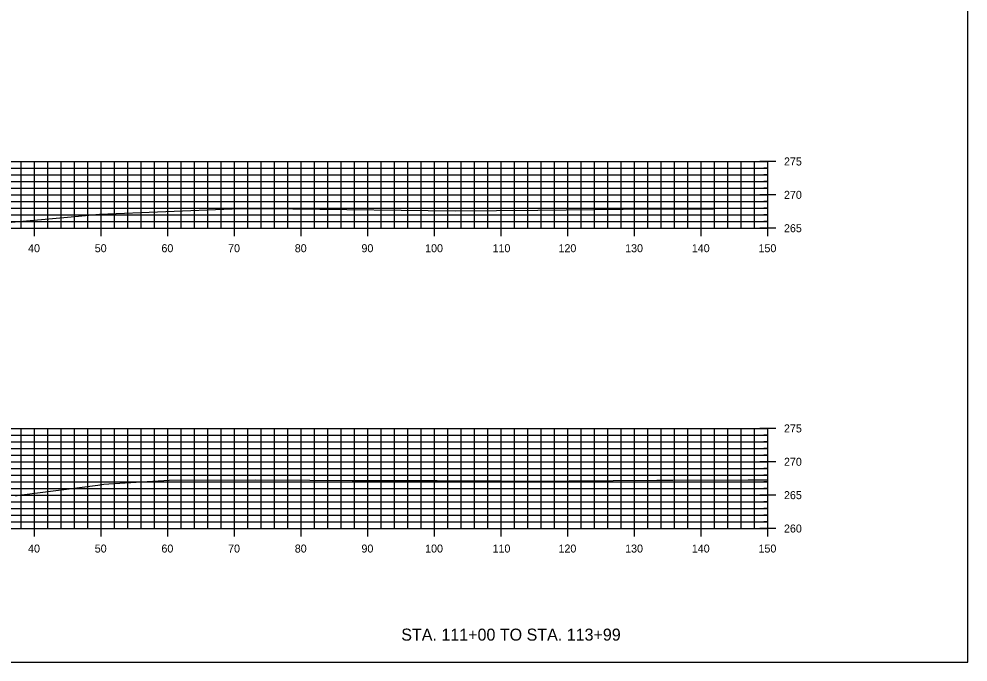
# Model space of a CAD drawing. Extents: x 1661012 to 1662122, y 670053 to 671852.
# Drawn here: x 1661629.7 to 1661772, y 671274.1 to 671370.5 of the extents above; entities that cross this region are included whole.
import ezdxf

# ---------------------------------------------------------------- set-up
doc = ezdxf.new("R2010")
doc.units = 0
for name, color, linetype in [('R_Concrete', 7, 'Continuous'), ('R_Concrete Hidden', 7, 'Continuous'), ('R_Erosion', 7, 'Continuous'), ('R_Exist Surface', 7, 'Continuous'), ('R_Proposed Road', 7, 'Continuous')]:
    doc.layers.add(name, color=color, linetype=linetype)

msp = doc.modelspace()

# ---------------------------------------------------------------- linework, layer by layer
at = {"layer": 'R_Concrete'}
for p, q in [((1661441.99, 671349.12), (1661741.99, 671349.12)), ((1661629.99, 671339.12), (1661629.99, 671349.12)), ((1661631.99, 671339.12), (1661631.99, 671349.12)), ((1661633.99, 671339.12), (1661633.99, 671349.12)), ((1661635.99, 671339.12), (1661635.99, 671349.12)), ((1661637.99, 671339.12), (1661637.99, 671349.12)), ((1661639.99, 671339.12), (1661639.99, 671349.12)), ((1661641.99, 671339.12), (1661641.99, 671349.12)), ((1661643.99, 671339.12), (1661643.99, 671349.12)), ((1661645.99, 671339.12), (1661645.99, 671349.12)), ((1661647.99, 671339.12), (1661647.99, 671349.12)), ((1661649.99, 671339.12), (1661649.99, 671349.12)), ((1661651.99, 671339.12), (1661651.99, 671349.12)), ((1661653.99, 671339.12), (1661653.99, 671349.12)), ((1661655.99, 671339.12), (1661655.99, 671349.12)), ((1661657.99, 671339.12), (1661657.99, 671349.12)), ((1661659.99, 671339.12), (1661659.99, 671349.12)), ((1661661.99, 671339.12), (1661661.99, 671349.12)), ((1661663.99, 671339.12), (1661663.99, 671349.12)), ((1661665.99, 671339.12), (1661665.99, 671349.12)), ((1661667.99, 671339.12), (1661667.99, 671349.12)), ((1661669.99, 671339.12), (1661669.99, 671349.12)), ((1661671.99, 671339.12), (1661671.99, 671349.12)), ((1661673.99, 671339.12), (1661673.99, 671349.12)), ((1661675.99, 671339.12), (1661675.99, 671349.12)), ((1661677.99, 671339.12), (1661677.99, 671349.12)), ((1661679.99, 671339.12), (1661679.99, 671349.12)), ((1661681.99, 671339.12), (1661681.99, 671349.12)), ((1661683.99, 671339.12), (1661683.99, 671349.12)), ((1661685.99, 671339.12), (1661685.99, 671349.12)), ((1661687.99, 671339.12), (1661687.99, 671349.12)), ((1661689.99, 671339.12), (1661689.99, 671349.12)), ((1661691.99, 671339.12), (1661691.99, 671349.12)), ((1661693.99, 671339.12), (1661693.99, 671349.12)), ((1661695.99, 671339.12), (1661695.99, 671349.12)), ((1661697.99, 671339.12), (1661697.99, 671349.12)), ((1661699.99, 671339.12), (1661699.99, 671349.12)), ((1661701.99, 671339.12), (1661701.99, 671349.12)), ((1661703.99, 671339.12), (1661703.99, 671349.12)), ((1661705.99, 671339.12), (1661705.99, 671349.12)), ((1661707.99, 671339.12), (1661707.99, 671349.12)), ((1661709.99, 671339.12), (1661709.99, 671349.12)), ((1661711.99, 671339.12), (1661711.99, 671349.12)), ((1661713.99, 671339.12), (1661713.99, 671349.12)), ((1661715.99, 671339.12), (1661715.99, 671349.12)), ((1661717.99, 671339.12), (1661717.99, 671349.12)), ((1661719.99, 671339.12), (1661719.99, 671349.12)), ((1661721.99, 671339.12), (1661721.99, 671349.12)), ((1661723.99, 671339.12), (1661723.99, 671349.12)), ((1661725.99, 671339.12), (1661725.99, 671349.12)), ((1661727.99, 671339.12), (1661727.99, 671349.12)), ((1661729.99, 671339.12), (1661729.99, 671349.12)), ((1661731.99, 671339.12), (1661731.99, 671349.12)), ((1661733.99, 671339.12), (1661733.99, 671349.12)), ((1661735.99, 671339.12), (1661735.99, 671349.12)), ((1661737.99, 671339.12), (1661737.99, 671349.12)), ((1661739.99, 671339.12), (1661739.99, 671349.12)), ((1661743.19, 671349.12), (1661740.79, 671349.12)), ((1661741.99, 671339.12), (1661741.99, 671349.12)), ((1661441.99, 671348.12), (1661741.99, 671348.12)), ((1661441.99, 671347.12), (1661741.99, 671347.12)), ((1661741.99, 671348.12), (1661741.39, 671348.12)), ((1661741.99, 671347.12), (1661741.39, 671347.12)), ((1661441.99, 671346.12), (1661741.99, 671346.12)), ((1661741.99, 671346.12), (1661741.39, 671346.12)), ((1661441.99, 671345.12), (1661741.99, 671345.12)), ((1661441.99, 671344.12), (1661741.99, 671344.12)), ((1661743.19, 671344.12), (1661740.79, 671344.12)), ((1661741.99, 671345.12), (1661741.39, 671345.12)), ((1661441.99, 671343.12), (1661741.99, 671343.12)), ((1661741.99, 671343.12), (1661741.39, 671343.12)), ((1661441.99, 671342.12), (1661741.99, 671342.12)), ((1661441.99, 671341.12), (1661741.99, 671341.12)), ((1661741.99, 671342.12), (1661741.39, 671342.12)), ((1661741.99, 671341.12), (1661741.39, 671341.12)), ((1661441.99, 671340.12), (1661741.99, 671340.12)), ((1661629.99, 671339.12), (1661629.99, 671339.72)), ((1661631.99, 671337.92), (1661631.99, 671340.32)), ((1661633.99, 671339.12), (1661633.99, 671339.72)), ((1661635.99, 671339.12), (1661635.99, 671339.72)), ((1661637.99, 671339.12), (1661637.99, 671339.72)), ((1661639.99, 671339.12), (1661639.99, 671339.72)), ((1661641.99, 671337.92), (1661641.99, 671340.32)), ((1661643.99, 671339.12), (1661643.99, 671339.72)), ((1661645.99, 671339.12), (1661645.99, 671339.72)), ((1661647.99, 671339.12), (1661647.99, 671339.72)), ((1661649.99, 671339.12), (1661649.99, 671339.72)), ((1661651.99, 671337.92), (1661651.99, 671340.32)), ((1661653.99, 671339.12), (1661653.99, 671339.72)), ((1661655.99, 671339.12), (1661655.99, 671339.72)), ((1661657.99, 671339.12), (1661657.99, 671339.72)), ((1661659.99, 671339.12), (1661659.99, 671339.72)), ((1661661.99, 671337.92), (1661661.99, 671340.32)), ((1661663.99, 671339.12), (1661663.99, 671339.72)), ((1661665.99, 671339.12), (1661665.99, 671339.72)), ((1661667.99, 671339.12), (1661667.99, 671339.72)), ((1661669.99, 671339.12), (1661669.99, 671339.72)), ((1661671.99, 671337.92), (1661671.99, 671340.32)), ((1661673.99, 671339.12), (1661673.99, 671339.72)), ((1661675.99, 671339.12), (1661675.99, 671339.72)), ((1661677.99, 671339.12), (1661677.99, 671339.72)), ((1661679.99, 671339.12), (1661679.99, 671339.72)), ((1661681.99, 671337.92), (1661681.99, 671340.32)), ((1661683.99, 671339.12), (1661683.99, 671339.72)), ((1661685.99, 671339.12), (1661685.99, 671339.72)), ((1661687.99, 671339.12), (1661687.99, 671339.72)), ((1661689.99, 671339.12), (1661689.99, 671339.72)), ((1661691.99, 671337.92), (1661691.99, 671340.32)), ((1661693.99, 671339.12), (1661693.99, 671339.72)), ((1661695.99, 671339.12), (1661695.99, 671339.72)), ((1661697.99, 671339.12), (1661697.99, 671339.72)), ((1661699.99, 671339.12), (1661699.99, 671339.72)), ((1661701.99, 671337.92), (1661701.99, 671340.32)), ((1661703.99, 671339.12), (1661703.99, 671339.72)), ((1661705.99, 671339.12), (1661705.99, 671339.72)), ((1661707.99, 671339.12), (1661707.99, 671339.72)), ((1661709.99, 671339.12), (1661709.99, 671339.72)), ((1661711.99, 671337.92), (1661711.99, 671340.32)), ((1661713.99, 671339.12), (1661713.99, 671339.72)), ((1661715.99, 671339.12), (1661715.99, 671339.72)), ((1661717.99, 671339.12), (1661717.99, 671339.72)), ((1661719.99, 671339.12), (1661719.99, 671339.72)), ((1661721.99, 671337.92), (1661721.99, 671340.32)), ((1661723.99, 671339.12), (1661723.99, 671339.72)), ((1661725.99, 671339.12), (1661725.99, 671339.72)), ((1661727.99, 671339.12), (1661727.99, 671339.72)), ((1661729.99, 671339.12), (1661729.99, 671339.72)), ((1661731.99, 671337.92), (1661731.99, 671340.32)), ((1661733.99, 671339.12), (1661733.99, 671339.72)), ((1661735.99, 671339.12), (1661735.99, 671339.72)), ((1661737.99, 671339.12), (1661737.99, 671339.72)), ((1661739.99, 671339.12), (1661739.99, 671339.72)), ((1661741.99, 671340.12), (1661741.39, 671340.12)), ((1661741.99, 671337.92), (1661741.99, 671340.32)), ((1661441.99, 671339.12), (1661741.99, 671339.12)), ((1661743.19, 671339.12), (1661740.79, 671339.12)), ((1661441.99, 671309.12), (1661741.99, 671309.12)), ((1661629.99, 671294.12), (1661629.99, 671309.12)), ((1661631.99, 671294.12), (1661631.99, 671309.12)), ((1661633.99, 671294.12), (1661633.99, 671309.12)), ((1661635.99, 671294.12), (1661635.99, 671309.12)), ((1661637.99, 671294.12), (1661637.99, 671309.12)), ((1661639.99, 671294.12), (1661639.99, 671309.12)), ((1661641.99, 671294.12), (1661641.99, 671309.12)), ((1661643.99, 671294.12), (1661643.99, 671309.12)), ((1661645.99, 671294.12), (1661645.99, 671309.12)), ((1661647.99, 671294.12), (1661647.99, 671309.12)), ((1661649.99, 671294.12), (1661649.99, 671309.12)), ((1661651.99, 671294.12), (1661651.99, 671309.12)), ((1661653.99, 671294.12), (1661653.99, 671309.12)), ((1661655.99, 671294.12), (1661655.99, 671309.12)), ((1661657.99, 671294.12), (1661657.99, 671309.12)), ((1661659.99, 671294.12), (1661659.99, 671309.12)), ((1661661.99, 671294.12), (1661661.99, 671309.12)), ((1661663.99, 671294.12), (1661663.99, 671309.12)), ((1661665.99, 671294.12), (1661665.99, 671309.12)), ((1661667.99, 671294.12), (1661667.99, 671309.12)), ((1661669.99, 671294.12), (1661669.99, 671309.12)), ((1661671.99, 671294.12), (1661671.99, 671309.12)), ((1661673.99, 671294.12), (1661673.99, 671309.12)), ((1661675.99, 671294.12), (1661675.99, 671309.12)), ((1661677.99, 671294.12), (1661677.99, 671309.12)), ((1661679.99, 671294.12), (1661679.99, 671309.12)), ((1661681.99, 671294.12), (1661681.99, 671309.12)), ((1661683.99, 671294.12), (1661683.99, 671309.12)), ((1661685.99, 671294.12), (1661685.99, 671309.12)), ((1661687.99, 671294.12), (1661687.99, 671309.12)), ((1661689.99, 671294.12), (1661689.99, 671309.12)), ((1661691.99, 671294.12), (1661691.99, 671309.12)), ((1661693.99, 671294.12), (1661693.99, 671309.12)), ((1661695.99, 671294.12), (1661695.99, 671309.12)), ((1661697.99, 671294.12), (1661697.99, 671309.12)), ((1661699.99, 671294.12), (1661699.99, 671309.12)), ((1661701.99, 671294.12), (1661701.99, 671309.12)), ((1661703.99, 671294.12), (1661703.99, 671309.12)), ((1661705.99, 671294.12), (1661705.99, 671309.12)), ((1661707.99, 671294.12), (1661707.99, 671309.12)), ((1661709.99, 671294.12), (1661709.99, 671309.12)), ((1661711.99, 671294.12), (1661711.99, 671309.12)), ((1661713.99, 671294.12), (1661713.99, 671309.12)), ((1661715.99, 671294.12), (1661715.99, 671309.12)), ((1661717.99, 671294.12), (1661717.99, 671309.12)), ((1661719.99, 671294.12), (1661719.99, 671309.12)), ((1661721.99, 671294.12), (1661721.99, 671309.12)), ((1661723.99, 671294.12), (1661723.99, 671309.12)), ((1661725.99, 671294.12), (1661725.99, 671309.12)), ((1661727.99, 671294.12), (1661727.99, 671309.12)), ((1661729.99, 671294.12), (1661729.99, 671309.12)), ((1661731.99, 671294.12), (1661731.99, 671309.12)), ((1661733.99, 671294.12), (1661733.99, 671309.12)), ((1661735.99, 671294.12), (1661735.99, 671309.12)), ((1661737.99, 671294.12), (1661737.99, 671309.12)), ((1661739.99, 671294.12), (1661739.99, 671309.12)), ((1661743.19, 671309.12), (1661740.79, 671309.12)), ((1661741.99, 671294.12), (1661741.99, 671309.12)), ((1661441.99, 671308.12), (1661741.99, 671308.12)), ((1661441.99, 671307.12), (1661741.99, 671307.12)), ((1661741.99, 671308.12), (1661741.39, 671308.12)), ((1661741.99, 671307.12), (1661741.39, 671307.12)), ((1661441.99, 671306.12), (1661741.99, 671306.12)), ((1661741.99, 671306.12), (1661741.39, 671306.12)), ((1661441.99, 671305.12), (1661741.99, 671305.12)), ((1661441.99, 671304.12), (1661741.99, 671304.12)), ((1661743.19, 671304.12), (1661740.79, 671304.12)), ((1661741.99, 671305.12), (1661741.39, 671305.12)), ((1661441.99, 671303.12), (1661741.99, 671303.12)), ((1661741.99, 671303.12), (1661741.39, 671303.12)), ((1661441.99, 671302.12), (1661741.99, 671302.12)), ((1661741.99, 671302.12), (1661741.39, 671302.12)), ((1661441.99, 671301.12), (1661741.99, 671301.12)), ((1661441.99, 671300.12), (1661741.99, 671300.12)), ((1661741.99, 671301.12), (1661741.39, 671301.12)), ((1661741.99, 671300.12), (1661741.39, 671300.12)), ((1661441.99, 671299.12), (1661741.99, 671299.12)), ((1661743.19, 671299.12), (1661740.79, 671299.12)), ((1661441.99, 671298.12), (1661741.99, 671298.12)), ((1661441.99, 671297.12), (1661741.99, 671297.12)), ((1661741.99, 671298.12), (1661741.39, 671298.12)), ((1661741.99, 671297.12), (1661741.39, 671297.12)), ((1661441.99, 671296.12), (1661741.99, 671296.12)), ((1661741.99, 671296.12), (1661741.39, 671296.12)), ((1661441.99, 671295.12), (1661741.99, 671295.12)), ((1661441.99, 671294.12), (1661741.99, 671294.12)), ((1661629.99, 671294.12), (1661629.99, 671294.72)), ((1661631.99, 671292.92), (1661631.99, 671295.32)), ((1661633.99, 671294.12), (1661633.99, 671294.72)), ((1661635.99, 671294.12), (1661635.99, 671294.72)), ((1661637.99, 671294.12), (1661637.99, 671294.72)), ((1661639.99, 671294.12), (1661639.99, 671294.72)), ((1661641.99, 671292.92), (1661641.99, 671295.32)), ((1661643.99, 671294.12), (1661643.99, 671294.72)), ((1661645.99, 671294.12), (1661645.99, 671294.72)), ((1661647.99, 671294.12), (1661647.99, 671294.72)), ((1661649.99, 671294.12), (1661649.99, 671294.72)), ((1661651.99, 671292.92), (1661651.99, 671295.32)), ((1661653.99, 671294.12), (1661653.99, 671294.72)), ((1661655.99, 671294.12), (1661655.99, 671294.72)), ((1661657.99, 671294.12), (1661657.99, 671294.72)), ((1661659.99, 671294.12), (1661659.99, 671294.72)), ((1661661.99, 671292.92), (1661661.99, 671295.32)), ((1661663.99, 671294.12), (1661663.99, 671294.72)), ((1661665.99, 671294.12), (1661665.99, 671294.72)), ((1661667.99, 671294.12), (1661667.99, 671294.72)), ((1661669.99, 671294.12), (1661669.99, 671294.72)), ((1661671.99, 671292.92), (1661671.99, 671295.32)), ((1661673.99, 671294.12), (1661673.99, 671294.72)), ((1661675.99, 671294.12), (1661675.99, 671294.72)), ((1661677.99, 671294.12), (1661677.99, 671294.72)), ((1661679.99, 671294.12), (1661679.99, 671294.72)), ((1661681.99, 671292.92), (1661681.99, 671295.32)), ((1661683.99, 671294.12), (1661683.99, 671294.72)), ((1661685.99, 671294.12), (1661685.99, 671294.72)), ((1661687.99, 671294.12), (1661687.99, 671294.72)), ((1661689.99, 671294.12), (1661689.99, 671294.72)), ((1661691.99, 671292.92), (1661691.99, 671295.32)), ((1661693.99, 671294.12), (1661693.99, 671294.72)), ((1661695.99, 671294.12), (1661695.99, 671294.72)), ((1661697.99, 671294.12), (1661697.99, 671294.72)), ((1661699.99, 671294.12), (1661699.99, 671294.72)), ((1661701.99, 671292.92), (1661701.99, 671295.32)), ((1661703.99, 671294.12), (1661703.99, 671294.72)), ((1661705.99, 671294.12), (1661705.99, 671294.72)), ((1661707.99, 671294.12), (1661707.99, 671294.72)), ((1661709.99, 671294.12), (1661709.99, 671294.72)), ((1661711.99, 671292.92), (1661711.99, 671295.32)), ((1661713.99, 671294.12), (1661713.99, 671294.72)), ((1661715.99, 671294.12), (1661715.99, 671294.72)), ((1661717.99, 671294.12), (1661717.99, 671294.72)), ((1661719.99, 671294.12), (1661719.99, 671294.72)), ((1661721.99, 671292.92), (1661721.99, 671295.32)), ((1661723.99, 671294.12), (1661723.99, 671294.72)), ((1661725.99, 671294.12), (1661725.99, 671294.72)), ((1661727.99, 671294.12), (1661727.99, 671294.72)), ((1661729.99, 671294.12), (1661729.99, 671294.72)), ((1661731.99, 671292.92), (1661731.99, 671295.32)), ((1661733.99, 671294.12), (1661733.99, 671294.72)), ((1661735.99, 671294.12), (1661735.99, 671294.72)), ((1661737.99, 671294.12), (1661737.99, 671294.72)), ((1661739.99, 671294.12), (1661739.99, 671294.72)), ((1661743.19, 671294.12), (1661740.79, 671294.12)), ((1661741.99, 671295.12), (1661741.39, 671295.12)), ((1661741.99, 671292.92), (1661741.99, 671295.32))]:
    msp.add_line(p, q, dxfattribs=at)
at = {"layer": 'R_Erosion'}
for points in [[(1661627.45, 671339.95), (1661638.01, 671340.88), (1661641.73, 671341.25), (1661661.64, 671342.01), (1661664.7, 671342.07), (1661670.72, 671342.01), (1661695.08, 671341.74), (1661707.45, 671341.83), (1661724.52, 671342.01), (1661733.77, 671341.99)], [(1661629.13, 671299.04), (1661629.66, 671299.12), (1661630.06, 671299.15), (1661641.46, 671300.63), (1661642.37, 671300.75), (1661643.11, 671300.83), (1661652.2, 671301.36), (1661665.13, 671301.4), (1661673.28, 671301.37), (1661679.63, 671301.33), (1661692.38, 671301.33), (1661701.85, 671301.25), (1661705.6, 671301.23), (1661725.33, 671301.39), (1661727.7, 671301.38), (1661739, 671301.41), (1661740.8, 671301.41), (1661741.99, 671301.42)]]:
    msp.add_lwpolyline(points, dxfattribs=at)
at = {"layer": 'R_Exist Surface'}
for p, q in [((1661741.99, 671339.12), (1661741.99, 671349.12)), ((1661441.99, 671339.12), (1661741.99, 671339.12)), ((1661741.99, 671294.12), (1661741.99, 671309.12)), ((1661441.99, 671294.12), (1661741.99, 671294.12))]:
    msp.add_line(p, q, dxfattribs=at)
at = {"layer": 'R_Proposed Road'}
msp.add_lwpolyline([(1661411.99, 671274.12), (1661771.99, 671274.12), (1661771.99, 671466.82), (1661411.99, 671466.82)], close=True, dxfattribs=at)

# ---------------------------------------------------------------- texts
at = {"layer": 'R_Concrete Hidden'}
for s, height, p in [('275', 1.2, (1661744.39, 671348.52)), ('270', 1.2, (1661744.39, 671343.52)), ('265', 1.2, (1661744.39, 671338.52)), ('40', 1.2, (1661631.02, 671335.52)), ('50', 1.2, (1661641.02, 671335.52)), ('60', 1.2, (1661651.02, 671335.52)), ('70', 1.2, (1661661.02, 671335.52)), ('80', 1.2, (1661671.02, 671335.52)), ('90', 1.2, (1661681.02, 671335.52)), ('100', 1.2, (1661690.57, 671335.52)), ('110', 1.2, (1661700.68, 671335.52)), ('120', 1.2, (1661710.57, 671335.52)), ('130', 1.2, (1661720.57, 671335.52)), ('140', 1.2, (1661730.57, 671335.52)), ('150', 1.2, (1661740.57, 671335.52)), ('275', 1.2, (1661744.39, 671308.52)), ('270', 1.2, (1661744.39, 671303.52)), ('265', 1.2, (1661744.39, 671298.52)), ('260', 1.2, (1661744.39, 671293.52)), ('40', 1.2, (1661631.02, 671290.52)), ('50', 1.2, (1661641.02, 671290.52)), ('60', 1.2, (1661651.02, 671290.52)), ('70', 1.2, (1661661.02, 671290.52)), ('80', 1.2, (1661671.02, 671290.52)), ('90', 1.2, (1661681.02, 671290.52)), ('100', 1.2, (1661690.57, 671290.52)), ('110', 1.2, (1661700.68, 671290.52)), ('120', 1.2, (1661710.57, 671290.52)), ('130', 1.2, (1661720.57, 671290.52)), ('140', 1.2, (1661730.57, 671290.52)), ('150', 1.2, (1661740.57, 671290.52)), ('STA. 111+00 TO STA. 113+99', 1.8, (1661686.99, 671277.32))]:
    msp.add_text(s, height=height, dxfattribs=at).set_placement(p)

doc.saveas('drawing.dxf')
